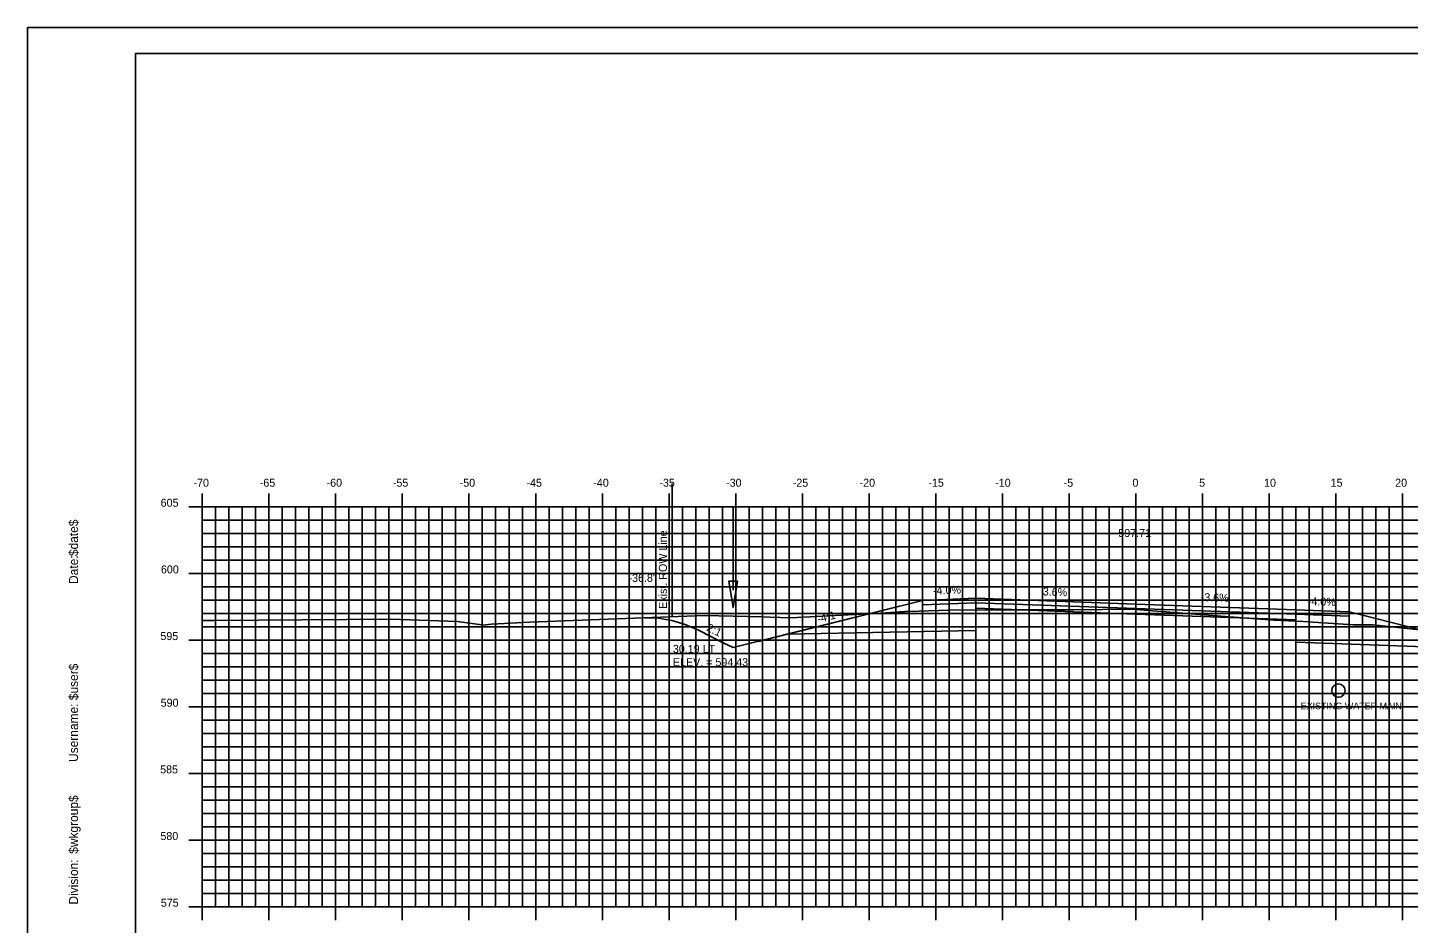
# Model space of a CAD drawing. Extents: x 1067877 to 1068047, y 779716 to 779826.
# Drawn here: x 1067877 to 1067980.5, y 779758.5 to 779825.6 of the extents above; entities that cross this region are included whole.
import ezdxf

# ---------------------------------------------------------------- set-up
doc = ezdxf.new("R2010")
doc.units = 0
for name, color, linetype in [('ANNOTATION', 7, 'Continuous'), ('BORDER', 7, 'Continuous'), ('D_Drainage_Ditch_Line', 7, 'Continuous'), ('D_Drainage_Text', 7, 'Continuous'), ('D_Roadway_Centerline', 7, 'Continuous'), ('D_Roadway_Centerline_Text', 7, 'Continuous'), ('D_Roadway_Edge_Pavement', 7, 'Continuous'), ('D_Roadway_Edge_Shoulder', 7, 'Continuous'), ('D_Roadway_Pavement', 7, 'Continuous'), ('D_Roadway_SlopeLines', 7, 'Continuous'), ('D_Roadway_SubGrade', 7, 'Continuous'), ('D_Text_Monospaced', 7, 'Continuous'), ('D_Text_Standard', 7, 'Continuous'), ('E_ROW_Line', 7, 'Continuous'), ('Existing Water Main', 7, 'Continuous'), ('H_V ANNOTATION', 7, 'Continuous'), ('MAJOR', 7, 'Continuous'), ('MINOR', 7, 'Continuous'), ('PLOT BOUNDARY', 7, 'Continuous'), ('S_Roadway_Centerline', 7, 'Continuous')]:
    doc.layers.add(name, color=color, linetype=linetype)

msp = doc.modelspace()

# ---------------------------------------------------------------- linework, layer by layer
at = {"layer": 'BORDER'}
msp.add_lwpolyline([(1067885.05, 779718.71), (1068045.05, 779718.71), (1068045.05, 779823.71), (1067885.05, 779823.71)], close=True, dxfattribs=at)
at = {"layer": 'D_Drainage_Ditch_Line'}
msp.add_line((1067929.85, 779783.46), (1067929.85, 779789.71), dxfattribs=at)
msp.add_lwpolyline([(1067929.53, 779784.12), (1067930.18, 779784.12), (1067929.85, 779782.15)], close=True, dxfattribs=at)
at = {"layer": 'D_Roadway_Centerline'}
for points in [[(1067944.05, 779782.68), (1067948.05, 779782.84), (1067960.05, 779782.41), (1067972.05, 779781.98), (1067976.05, 779781.82)], [(1067931.76, 779779.61), (1067933.89, 779780.14)]]:
    msp.add_lwpolyline(points, dxfattribs=at)
at = {"layer": 'D_Roadway_Edge_Pavement'}
msp.add_lwpolyline([(1067948.05, 779782.51), (1067948.05, 779782.84), (1067960.05, 779782.41), (1067972.05, 779781.98), (1067972.05, 779781.65), (1067960.05, 779782.08)], close=True, dxfattribs=at)
at = {"layer": 'D_Roadway_Edge_Shoulder'}
for points in [[(1067948.05, 779782.84), (1067944.05, 779782.68), (1067944.05, 779782.41), (1067944.05, 779782.35), (1067948.04, 779782.51)], [(1067972.05, 779781.98), (1067976.05, 779781.82), (1067976.05, 779781.49), (1067972.05, 779781.65)]]:
    msp.add_lwpolyline(points, close=True, dxfattribs=at)
at = {"layer": 'D_Roadway_Pavement'}
msp.add_lwpolyline([(1067948.05, 779782.09), (1067948.05, 779782.51), (1067960.05, 779782.08), (1067972.05, 779781.65), (1067972.05, 779781.23), (1067960.05, 779781.66)], close=True, dxfattribs=at)
at = {"layer": 'D_Roadway_SlopeLines'}
msp.add_line((1067944.05, 779782.68), (1067931.76, 779779.61), dxfattribs=at)
for points in [[(1067929.1, 779779.51), (1067927.25, 779780.44), (1067926.25, 779780.87), (1067925.25, 779781.17), (1067924.25, 779781.34), (1067923.25, 779781.37)], [(1067933.89, 779780.14), (1067929.85, 779779.14), (1067929.1, 779779.51)]]:
    msp.add_lwpolyline(points, dxfattribs=at)
at = {"layer": 'D_Roadway_SubGrade'}
for points in [[(1067948.05, 779780.43), (1067933.89, 779780.14), (1067944.05, 779782.68), (1067944.05, 779782.41), (1067944.05, 779782.35), (1067948.05, 779782.51), (1067948.05, 779782.35), (1067948.05, 779780.85)], [(1067972.05, 779780.15), (1067972.05, 779781.65), (1067972.05, 779781.65), (1067976.05, 779781.49), (1067976.05, 779781.82), (1067986.21, 779779.28), (1067987.26, 779779.01), (1067972.05, 779779.56)]]:
    msp.add_lwpolyline(points, close=True, dxfattribs=at)
at = {"layer": 'E_ROW_Line'}
msp.add_line((1067925.29, 779781.45), (1067925.29, 779791.45), dxfattribs=at)
msp.add_line((1067925.29, 779781.45), (1067925.29, 779791.45), dxfattribs=at)
at = {"layer": 'Existing Water Main'}
msp.add_lwpolyline([(1067975.25, 779775.92), (1067975.25, 779775.92)], dxfattribs=at)
msp.add_circle((1067975.25, 779775.92), 0.501, dxfattribs=at)
at = {"layer": 'MAJOR'}
for p, q in [((1067890.05, 779790.71), (1067890.05, 779789.71)), ((1067895.05, 779790.71), (1067895.05, 779789.71)), ((1067900.05, 779790.71), (1067900.05, 779789.71)), ((1067905.05, 779790.71), (1067905.05, 779789.71)), ((1067910.05, 779790.71), (1067910.05, 779789.71)), ((1067915.05, 779790.71), (1067915.05, 779789.71)), ((1067920.05, 779790.71), (1067920.05, 779789.71)), ((1067925.05, 779790.71), (1067925.05, 779789.71)), ((1067930.05, 779790.71), (1067930.05, 779789.71)), ((1067935.05, 779790.71), (1067935.05, 779789.71)), ((1067940.05, 779790.71), (1067940.05, 779789.71)), ((1067945.05, 779790.71), (1067945.05, 779789.71)), ((1067950.05, 779790.71), (1067950.05, 779789.71)), ((1067955.05, 779790.71), (1067955.05, 779789.71)), ((1067960.05, 779790.71), (1067960.05, 779789.71)), ((1067965.05, 779790.71), (1067965.05, 779789.71)), ((1067970.05, 779790.71), (1067970.05, 779789.71)), ((1067975.05, 779790.71), (1067975.05, 779789.71)), ((1067980.05, 779790.71), (1067980.05, 779789.71)), ((1067889.04, 779789.71), (1067890.05, 779789.71)), ((1067890.05, 779789.71), (1068030.05, 779789.71)), ((1067890.05, 779759.71), (1067890.05, 779789.71)), ((1067890.05, 779759.71), (1067890.05, 779789.71)), ((1067890.05, 779789.71), (1068030.05, 779789.71)), ((1067895.05, 779759.71), (1067895.05, 779789.71)), ((1067900.05, 779759.71), (1067900.05, 779789.71)), ((1067905.05, 779759.71), (1067905.05, 779789.71)), ((1067910.05, 779759.71), (1067910.05, 779789.71)), ((1067915.05, 779759.71), (1067915.05, 779789.71)), ((1067920.05, 779759.71), (1067920.05, 779789.71)), ((1067925.05, 779759.71), (1067925.05, 779789.71)), ((1067930.05, 779759.71), (1067930.05, 779789.71)), ((1067935.05, 779759.71), (1067935.05, 779789.71)), ((1067940.05, 779759.71), (1067940.05, 779789.71)), ((1067945.05, 779759.71), (1067945.05, 779789.71)), ((1067950.05, 779759.71), (1067950.05, 779789.71)), ((1067955.05, 779759.71), (1067955.05, 779789.71)), ((1067960.05, 779759.71), (1067960.05, 779789.71)), ((1067965.05, 779759.71), (1067965.05, 779789.71)), ((1067970.05, 779759.71), (1067970.05, 779789.71)), ((1067975.05, 779759.71), (1067975.05, 779789.71)), ((1067980.05, 779759.71), (1067980.05, 779789.71)), ((1067889.04, 779784.71), (1067890.05, 779784.71)), ((1067890.05, 779784.71), (1068030.05, 779784.71)), ((1067889.04, 779779.71), (1067890.05, 779779.71)), ((1067890.05, 779779.71), (1068030.05, 779779.71)), ((1067889.04, 779774.71), (1067890.05, 779774.71)), ((1067890.05, 779774.71), (1068030.05, 779774.71)), ((1067889.04, 779769.71), (1067890.05, 779769.71)), ((1067890.05, 779769.71), (1068030.05, 779769.71)), ((1067889.04, 779764.71), (1067890.05, 779764.71)), ((1067890.05, 779764.71), (1068030.05, 779764.71)), ((1067889.04, 779759.71), (1067890.05, 779759.71)), ((1067890.05, 779759.71), (1068030.05, 779759.71)), ((1067890.05, 779759.71), (1068030.05, 779759.71)), ((1067890.05, 779758.7), (1067890.05, 779759.71)), ((1067895.05, 779758.7), (1067895.05, 779759.71)), ((1067900.05, 779758.7), (1067900.05, 779759.71)), ((1067905.05, 779758.7), (1067905.05, 779759.71)), ((1067910.05, 779758.7), (1067910.05, 779759.71)), ((1067915.05, 779758.7), (1067915.05, 779759.71)), ((1067920.05, 779758.7), (1067920.05, 779759.71)), ((1067925.05, 779758.7), (1067925.05, 779759.71)), ((1067930.05, 779758.7), (1067930.05, 779759.71)), ((1067935.05, 779758.7), (1067935.05, 779759.71)), ((1067940.05, 779758.7), (1067940.05, 779759.71)), ((1067945.05, 779758.7), (1067945.05, 779759.71)), ((1067950.05, 779758.7), (1067950.05, 779759.71)), ((1067955.05, 779758.7), (1067955.05, 779759.71)), ((1067960.05, 779758.7), (1067960.05, 779759.71)), ((1067965.05, 779758.7), (1067965.05, 779759.71)), ((1067970.05, 779758.7), (1067970.05, 779759.71)), ((1067975.05, 779758.7), (1067975.05, 779759.71)), ((1067980.05, 779758.7), (1067980.05, 779759.71))]:
    msp.add_line(p, q, dxfattribs=at)
at = {"layer": 'MINOR'}
for p, q in [((1067891.05, 779759.71), (1067891.05, 779789.71)), ((1067892.05, 779759.71), (1067892.05, 779789.71)), ((1067893.05, 779759.71), (1067893.05, 779789.71)), ((1067894.05, 779759.71), (1067894.05, 779789.71)), ((1067896.05, 779759.71), (1067896.05, 779789.71)), ((1067897.05, 779759.71), (1067897.05, 779789.71)), ((1067898.05, 779759.71), (1067898.05, 779789.71)), ((1067899.05, 779759.71), (1067899.05, 779789.71)), ((1067901.05, 779759.71), (1067901.05, 779789.71)), ((1067902.05, 779759.71), (1067902.05, 779789.71)), ((1067903.05, 779759.71), (1067903.05, 779789.71)), ((1067904.05, 779759.71), (1067904.05, 779789.71)), ((1067906.05, 779759.71), (1067906.05, 779789.71)), ((1067907.05, 779759.71), (1067907.05, 779789.71)), ((1067908.05, 779759.71), (1067908.05, 779789.71)), ((1067909.05, 779759.71), (1067909.05, 779789.71)), ((1067911.05, 779759.71), (1067911.05, 779789.71)), ((1067912.05, 779759.71), (1067912.05, 779789.71)), ((1067913.05, 779759.71), (1067913.05, 779789.71)), ((1067914.05, 779759.71), (1067914.05, 779789.71)), ((1067916.05, 779759.71), (1067916.05, 779789.71)), ((1067917.05, 779759.71), (1067917.05, 779789.71)), ((1067918.05, 779759.71), (1067918.05, 779789.71)), ((1067919.05, 779759.71), (1067919.05, 779789.71)), ((1067921.05, 779759.71), (1067921.05, 779789.71)), ((1067922.05, 779759.71), (1067922.05, 779789.71)), ((1067923.05, 779759.71), (1067923.05, 779789.71)), ((1067924.05, 779759.71), (1067924.05, 779789.71)), ((1067926.05, 779759.71), (1067926.05, 779789.71)), ((1067927.05, 779759.71), (1067927.05, 779789.71)), ((1067928.05, 779759.71), (1067928.05, 779789.71)), ((1067929.05, 779759.71), (1067929.05, 779789.71)), ((1067931.05, 779759.71), (1067931.05, 779789.71)), ((1067932.05, 779759.71), (1067932.05, 779789.71)), ((1067933.05, 779759.71), (1067933.05, 779789.71)), ((1067934.05, 779759.71), (1067934.05, 779789.71)), ((1067936.05, 779759.71), (1067936.05, 779789.71)), ((1067937.05, 779759.71), (1067937.05, 779789.71)), ((1067938.05, 779759.71), (1067938.05, 779789.71)), ((1067939.05, 779759.71), (1067939.05, 779789.71)), ((1067941.05, 779759.71), (1067941.05, 779789.71)), ((1067942.05, 779759.71), (1067942.05, 779789.71)), ((1067943.05, 779759.71), (1067943.05, 779789.71)), ((1067944.05, 779759.71), (1067944.05, 779789.71)), ((1067946.05, 779759.71), (1067946.05, 779789.71)), ((1067947.05, 779759.71), (1067947.05, 779789.71)), ((1067948.05, 779759.71), (1067948.05, 779789.71)), ((1067949.05, 779759.71), (1067949.05, 779789.71)), ((1067951.05, 779759.71), (1067951.05, 779789.71)), ((1067952.05, 779759.71), (1067952.05, 779789.71)), ((1067953.05, 779759.71), (1067953.05, 779789.71)), ((1067954.05, 779759.71), (1067954.05, 779789.71)), ((1067956.05, 779759.71), (1067956.05, 779789.71)), ((1067957.05, 779759.71), (1067957.05, 779789.71)), ((1067958.05, 779759.71), (1067958.05, 779789.71)), ((1067959.05, 779759.71), (1067959.05, 779789.71)), ((1067961.05, 779759.71), (1067961.05, 779789.71)), ((1067962.05, 779759.71), (1067962.05, 779789.71)), ((1067963.05, 779759.71), (1067963.05, 779789.71)), ((1067964.05, 779759.71), (1067964.05, 779789.71)), ((1067966.05, 779759.71), (1067966.05, 779789.71)), ((1067967.05, 779759.71), (1067967.05, 779789.71)), ((1067968.05, 779759.71), (1067968.05, 779789.71)), ((1067969.05, 779759.71), (1067969.05, 779789.71)), ((1067971.05, 779759.71), (1067971.05, 779789.71)), ((1067972.05, 779759.71), (1067972.05, 779789.71)), ((1067973.05, 779759.71), (1067973.05, 779789.71)), ((1067974.05, 779759.71), (1067974.05, 779789.71)), ((1067976.05, 779759.71), (1067976.05, 779789.71)), ((1067977.05, 779759.71), (1067977.05, 779789.71)), ((1067978.05, 779759.71), (1067978.05, 779789.71)), ((1067979.05, 779759.71), (1067979.05, 779789.71)), ((1067890.05, 779788.71), (1068030.05, 779788.71)), ((1067890.05, 779788.71), (1067891.05, 779788.71)), ((1067890.05, 779787.71), (1068030.05, 779787.71)), ((1067890.05, 779787.71), (1067891.05, 779787.71)), ((1067890.05, 779786.71), (1068030.05, 779786.71)), ((1067890.05, 779786.71), (1067891.05, 779786.71)), ((1067890.05, 779785.71), (1068030.05, 779785.71)), ((1067890.05, 779785.71), (1067891.05, 779785.71)), ((1067890.05, 779783.71), (1068030.05, 779783.71)), ((1067890.05, 779783.71), (1067891.05, 779783.71)), ((1067890.05, 779782.71), (1068030.05, 779782.71)), ((1067890.05, 779782.71), (1067891.05, 779782.71)), ((1067890.05, 779781.71), (1068030.05, 779781.71)), ((1067890.05, 779781.71), (1067891.05, 779781.71)), ((1067890.05, 779780.71), (1068030.05, 779780.71)), ((1067890.05, 779780.71), (1067891.05, 779780.71)), ((1067890.05, 779778.71), (1068030.05, 779778.71)), ((1067890.05, 779778.71), (1067891.05, 779778.71)), ((1067890.05, 779777.71), (1068030.05, 779777.71)), ((1067890.05, 779777.71), (1067891.05, 779777.71)), ((1067890.05, 779776.71), (1068030.05, 779776.71)), ((1067890.05, 779776.71), (1067891.05, 779776.71)), ((1067890.05, 779775.71), (1068030.05, 779775.71)), ((1067890.05, 779775.71), (1067891.05, 779775.71)), ((1067890.05, 779773.71), (1068030.05, 779773.71)), ((1067890.05, 779773.71), (1067891.05, 779773.71)), ((1067890.05, 779772.71), (1068030.05, 779772.71)), ((1067890.05, 779772.71), (1067891.05, 779772.71)), ((1067890.05, 779771.71), (1068030.05, 779771.71)), ((1067890.05, 779771.71), (1067891.05, 779771.71)), ((1067890.05, 779770.71), (1068030.05, 779770.71)), ((1067890.05, 779770.71), (1067891.05, 779770.71)), ((1067890.05, 779768.71), (1068030.05, 779768.71)), ((1067890.05, 779768.71), (1067891.05, 779768.71)), ((1067890.05, 779767.71), (1068030.05, 779767.71)), ((1067890.05, 779767.71), (1067891.05, 779767.71)), ((1067890.05, 779766.71), (1068030.05, 779766.71)), ((1067890.05, 779766.71), (1067891.05, 779766.71)), ((1067890.05, 779765.71), (1068030.05, 779765.71)), ((1067890.05, 779765.71), (1067891.05, 779765.71)), ((1067890.05, 779763.71), (1068030.05, 779763.71)), ((1067890.05, 779763.71), (1067891.05, 779763.71)), ((1067890.05, 779762.71), (1068030.05, 779762.71)), ((1067890.05, 779762.71), (1067891.05, 779762.71)), ((1067890.05, 779761.71), (1068030.05, 779761.71)), ((1067890.05, 779761.71), (1067891.05, 779761.71)), ((1067890.05, 779760.71), (1068030.05, 779760.71)), ((1067890.05, 779760.71), (1067891.05, 779760.71))]:
    msp.add_line(p, q, dxfattribs=at)
at = {"layer": 'PLOT BOUNDARY'}
msp.add_lwpolyline([(1067876.95, 779715.65), (1068046.95, 779715.65), (1068046.95, 779825.65), (1067876.95, 779825.65)], close=True, dxfattribs=at)
at = {"layer": 'S_Roadway_Centerline'}
msp.add_lwpolyline([(1067890.05, 779781.18), (1067890.91, 779781.18), (1067904.19, 779781.28), (1067909.19, 779781.1), (1067911.01, 779780.86), (1067911.09, 779780.82), (1067911.73, 779780.9), (1067914.59, 779781.05), (1067927.72, 779781.54), (1067932.01, 779781.44), (1067932.63, 779781.42), (1067934.16, 779781.38), (1067941.36, 779781.76), (1067942.34, 779781.82), (1067942.71, 779781.83), (1067942.75, 779781.84), (1067942.81, 779781.85), (1067942.97, 779781.86), (1067946.06, 779781.95), (1067949.25, 779781.98), (1067955.37, 779781.97), (1067959.74, 779782.02), (1067967.11, 779781.46), (1067970.4, 779781.19), (1067972.61, 779781.1), (1067976.35, 779780.85), (1067977.84, 779780.84), (1067981.32, 779780.48)], dxfattribs=at)

# ---------------------------------------------------------------- texts
at = {"layer": 'ANNOTATION'}
for s, rotation, p in [('-4.0%', 2.2906, (1067944.86, 779783.12)), ('3.6%', 357.9382, (1067953.07, 779783.06)), ('-3.6%', 357.9382, (1067964.91, 779782.64)), ('-4.0%', 357.7094, (1067972.94, 779782.34)), ('-4:1', 14.0362, (1067936.24, 779780.99)), ('2:1', 333.4349, (1067927.81, 779780.44))]:
    msp.add_text(s, height=0.6, rotation=rotation, dxfattribs=at).set_placement(p)
at = {"layer": 'BORDER'}
for s, p in [('$date$', (1067880.73, 779786.01)), ('Date:', (1067880.73, 779783.92)), ('$user$', (1067880.73, 779775.2)), ('Username:', (1067880.73, 779770.57)), ('$wkgroup$', (1067880.73, 779763.68)), ('Division:', (1067880.73, 779759.87))]:
    msp.add_text(s, height=0.67, rotation=90, dxfattribs=at).set_placement(p)
at = {"layer": 'D_Drainage_Text'}
for s, p in [('30.19 LT', (1067925.34, 779778.75)), ('ELEV. = 594.43', (1067925.34, 779777.75))]:
    msp.add_text(s, height=0.6, dxfattribs=at).set_placement(p)
at = {"layer": 'D_Roadway_Centerline_Text'}
msp.add_text('597.71', height=0.6, dxfattribs=at).set_placement((1067958.74, 779787.44))
at = {"layer": 'D_Text_Monospaced'}
msp.add_text('EXISTING WATER MAIN', height=0.5, dxfattribs=at).set_placement((1067972.42, 779774.52))
at = {"layer": 'D_Text_Standard'}
msp.add_text("-36.8'", height=0.6, dxfattribs=at).set_placement((1067922.01, 779784.07))
at = {"layer": 'E_ROW_Line'}
msp.add_text('Exist. ROW Line', height=0.6, rotation=90, dxfattribs=at).set_placement((1067924.89, 779782.05))
at = {"layer": 'H_V ANNOTATION'}
for s, p in [('-70', (1067889.39, 779791.21)), ('-65', (1067894.36, 779791.21)), ('-60', (1067899.37, 779791.21)), ('-55', (1067904.34, 779791.21)), ('-50', (1067909.35, 779791.21)), ('-45', (1067914.36, 779791.21)), ('-40', (1067919.37, 779791.21)), ('-35', (1067924.33, 779791.21)), ('-30', (1067929.33, 779791.21)), ('-25', (1067934.33, 779791.21)), ('-20', (1067939.34, 779791.21)), ('-15', (1067944.5, 779791.21)), ('-10', (1067949.51, 779791.21)), ('-5', (1067954.64, 779791.21)), ('0', (1067959.8, 779791.21)), ('5', (1067964.8, 779791.21)), ('10', (1067969.67, 779791.21)), ('15', (1067974.66, 779791.21)), ('20', (1067979.5, 779791.21)), ('605', (1067886.93, 779789.71)), ('600', (1067886.95, 779784.71)), ('595', (1067886.91, 779779.71)), ('590', (1067886.93, 779774.71)), ('585', (1067886.89, 779769.71)), ('580', (1067886.91, 779764.71)), ('575', (1067886.94, 779759.71))]:
    msp.add_text(s, height=0.6, dxfattribs=at).set_placement(p)
at = {"layer": 'MAJOR'}
msp.add_text('-', height=0.006, dxfattribs=at).set_placement((1067890.04, 779759.71))

doc.saveas('drawing.dxf')
